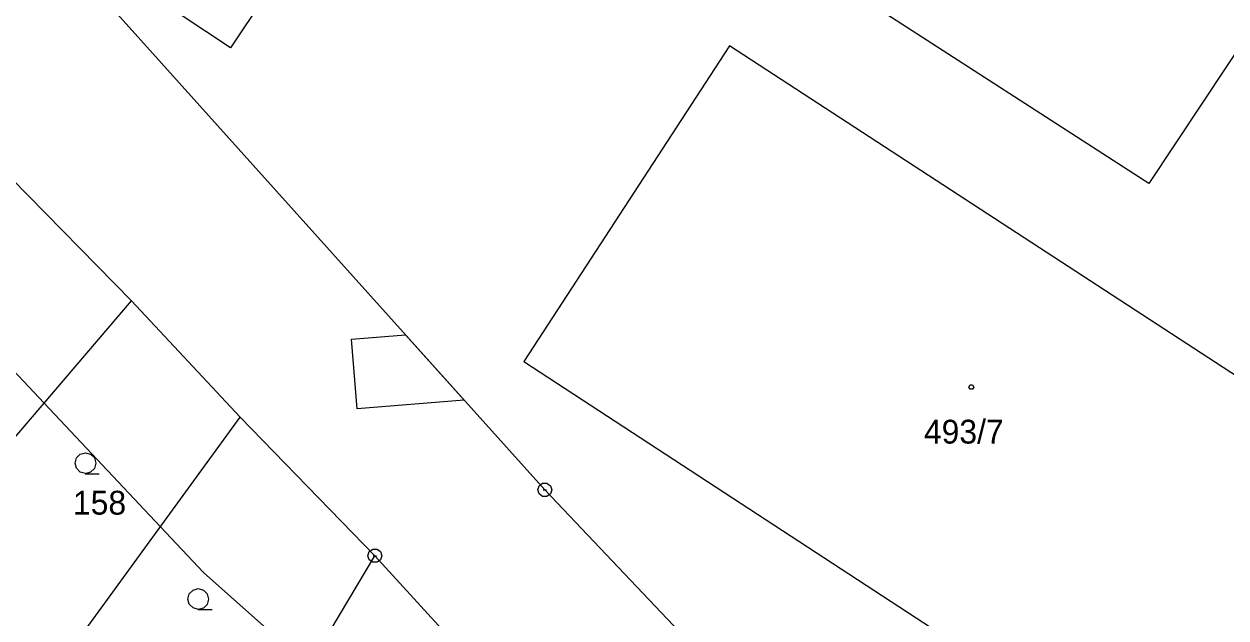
# Model space of a CAD drawing. Extents: x -755359 to -754474, y -1162585 to -1161655.
# Drawn here: x -754813.8 to -754728, y -1161826.3 to -1161783.9 of the extents above; entities that cross this region are included whole.
import ezdxf

# ---------------------------------------------------------------- set-up
doc = ezdxf.new("R2010")
doc.units = 0
for name, color, linetype in [('Vrstva 1', 7, 'Continuous'), ('Vrstva 11', 7, 'Continuous'), ('Vrstva 12', 7, 'Continuous'), ('Vrstva 13', 7, 'Continuous'), ('Vrstva 2', 7, 'Continuous'), ('Vrstva 3', 7, 'Continuous'), ('Vrstva 4', 7, 'Continuous'), ('Vrstva 5', 7, 'Continuous'), ('Vrstva 8', 7, 'Continuous')]:
    doc.layers.add(name, color=color, linetype=linetype)

msp = doc.modelspace()

# ---------------------------------------------------------------- linework, layer by layer
at = {"layer": 'Vrstva 1'}
for p, q in [((-754787.53, -1161768.2), (-754799.07, -1161785.58)), ((-754813.94, -1161775.57), (-754776.63, -1161817.12)), ((-754799.07, -1161785.58), (-754806.27, -1161780.78)), ((-754763.46, -1161785.44), (-754778.14, -1161807.96)), ((-754724.19, -1161811.01), (-754763.46, -1161785.44)), ((-754806.13, -1161803.63), (-754814.71, -1161794.87)), ((-754815.87, -1161815.02), (-754806.13, -1161803.63)), ((-754798.38, -1161811.92), (-754806.13, -1161803.63)), ((-754778.14, -1161807.96), (-754744.92, -1161829.64)), ((-754811.79, -1161830.35), (-754798.38, -1161811.92)), ((-754798.38, -1161811.92), (-754788.76, -1161821.82)), ((-754776.63, -1161817.12), (-754756.21, -1161838.63)), ((-754798.29, -1161837.8), (-754788.76, -1161821.82)), ((-754773.44, -1161838.56), (-754788.76, -1161821.82))]:
    msp.add_line(p, q, dxfattribs=at)
at = {"layer": 'Vrstva 11'}
for p, q in [((-754820.81, -1161801.96), (-754812.37, -1161810.92)), ((-754812.37, -1161810.92), (-754804.07, -1161819.74)), ((-754804.07, -1161819.74), (-754800.99, -1161823.01)), ((-754800.99, -1161823.01), (-754793.46, -1161829.69))]:
    msp.add_line(p, q, dxfattribs=at)
at = {"layer": 'Vrstva 12'}
for p, q in [((-754787.53, -1161768.2), (-754799.07, -1161785.58)), ((-754799.07, -1161785.58), (-754806.27, -1161780.78)), ((-754763.46, -1161785.44), (-754778.14, -1161807.96)), ((-754724.19, -1161811.01), (-754763.46, -1161785.44)), ((-754778.14, -1161807.96), (-754744.92, -1161829.64))]:
    msp.add_line(p, q, dxfattribs=at)
at = {"layer": 'Vrstva 13'}
for p, q in [((-754790.43, -1161806.35), (-754786.58, -1161806.04)), ((-754786.58, -1161806.04), (-754782.39, -1161810.71)), ((-754790.02, -1161811.34), (-754790.43, -1161806.35)), ((-754782.39, -1161810.71), (-754790.02, -1161811.34))]:
    msp.add_line(p, q, dxfattribs=at)
at = {"layer": 'Vrstva 3'}
for points in [[(-754809.41, -1161815.94), (-754809.79, -1161815.84), (-754810.06, -1161815.57), (-754810.16, -1161815.2), (-754810.06, -1161814.83), (-754809.79, -1161814.56), (-754809.42, -1161814.46), (-754809.05, -1161814.56), (-754808.78, -1161814.83), (-754808.68, -1161815.21), (-754808.78, -1161815.59), (-754809.05, -1161815.86), (-754809.43, -1161815.96), (-754808.43, -1161815.96)], [(-754801.36, -1161825.64), (-754801.74, -1161825.54), (-754802.01, -1161825.27), (-754802.11, -1161824.9), (-754802.01, -1161824.53), (-754801.74, -1161824.26), (-754801.37, -1161824.16), (-754801, -1161824.26), (-754800.73, -1161824.53), (-754800.63, -1161824.91), (-754800.73, -1161825.29), (-754801, -1161825.56), (-754801.38, -1161825.66), (-754800.38, -1161825.66)]]:
    msp.add_lwpolyline(points, dxfattribs=at)
at = {"layer": 'Vrstva 4'}
for p, q in [((-754679.82, -1161714.24), (-754733.53, -1161795.26)), ((-754733.53, -1161795.26), (-754782.49, -1161763.64))]:
    msp.add_line(p, q, dxfattribs=at)
at = {"layer": 'Vrstva 5'}
msp.add_lwpolyline([(-754746.11, -1161809.63), (-754746.02, -1161809.78), (-754746.11, -1161809.93), (-754746.29, -1161809.93), (-754746.38, -1161809.78), (-754746.29, -1161809.63)], close=True, dxfattribs=at)
at = {"layer": 'Vrstva 8'}
for p, q in [((-754776.75, -1161817.12), (-754776.51, -1161817.12)), ((-754788.88, -1161821.82), (-754788.64, -1161821.82))]:
    msp.add_line(p, q, dxfattribs=at)
for points in [[(-754776.48, -1161816.64), (-754776.23, -1161816.82), (-754776.13, -1161817.11), (-754776.23, -1161817.4), (-754776.48, -1161817.58), (-754776.79, -1161817.58), (-754777.04, -1161817.4), (-754777.14, -1161817.11), (-754777.04, -1161816.82), (-754776.79, -1161816.64)], [(-754788.61, -1161821.34), (-754788.36, -1161821.52), (-754788.26, -1161821.81), (-754788.36, -1161822.1), (-754788.61, -1161822.28), (-754788.92, -1161822.28), (-754789.17, -1161822.1), (-754789.27, -1161821.81), (-754789.17, -1161821.52), (-754788.92, -1161821.34)]]:
    msp.add_lwpolyline(points, close=True, dxfattribs=at)

# ---------------------------------------------------------------- texts
at = {"layer": 'Vrstva 2'}
for s, p in [('493/7', (-754749.58, -1161813.81)), ('158', (-754810.307, -1161818.88))]:
    msp.add_text(s, height=1.7, dxfattribs=at).set_placement(p)

doc.saveas('drawing.dxf')
